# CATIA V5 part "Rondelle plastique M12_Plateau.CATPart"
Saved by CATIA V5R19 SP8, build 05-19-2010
Part number: Rondelle plastique M12
Nomenclature: 106
Material "Plastique": density 1200 kg/m3, Young's modulus 2.2e+09 Pa, Poisson ratio 0.38, thermal expansion 6.84e-05 1/K
Bounding box of the stored display mesh (mm): x 0 to 1, y -10.5 to 10.5, z -10.5 to 10.5
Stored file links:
  C:\Users\rphgr\Desktop\0_Tapis_TC520B_vitesse\Rondelle plastique M12_Plateau.CATPart
  D:\Programmes\DassaultSysteme\win_b64\startup\materials\French\Catalog.CATMaterial
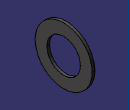
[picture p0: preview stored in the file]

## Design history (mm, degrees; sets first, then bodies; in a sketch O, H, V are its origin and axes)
AxisSystem1: origin (0, 0, 0), X (1, 0, 0), Y (0, 1, 0), Z (0, 0, 1)
Body1 (main body), material "Plastique"
  Sketch1 on YZ plane of AxisSystem1, origin (0, 0, 0), H (0, 1, 0), V (0, 0, 1)
    circle A1 centre (0, 0) radius 6.2
    circle A2 centre (0, 0) radius 10.5
    radius A2 = 10.5
    radius A1 = 6.2
  Pad1: profile Sketch1, direction (1, 0, 0), length 1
